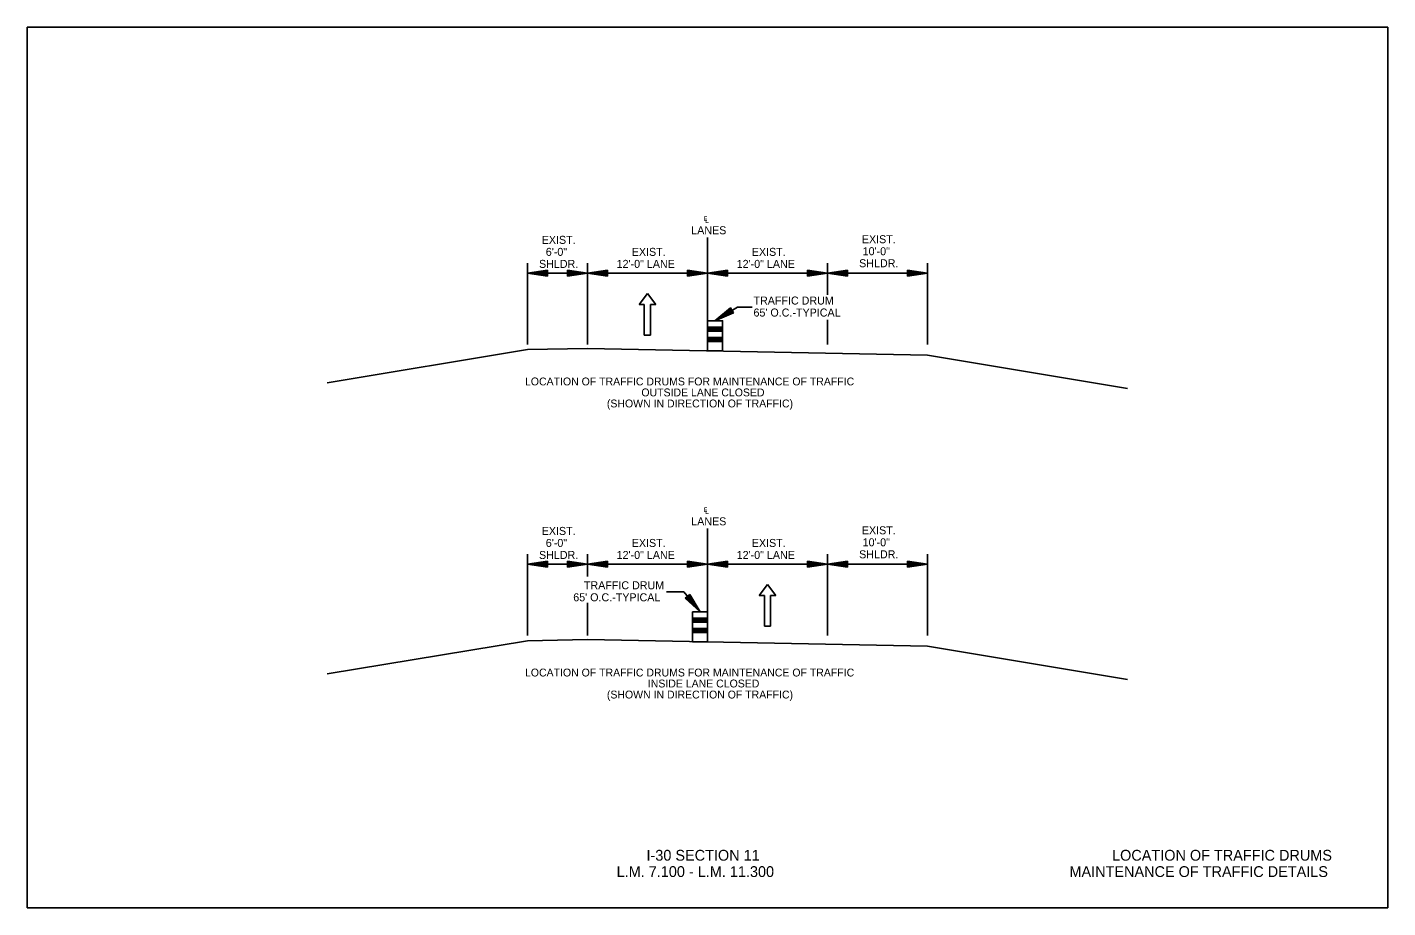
# Model space of a CAD drawing. Extents: x 1374027 to 1374537, y 380415 to 381405.
# Drawn here: x 1374027.1 to 1374197.1, y 380415.2 to 380525.2 of the extents above; entities that cross this region are included whole.
import ezdxf

# ---------------------------------------------------------------- set-up
doc = ezdxf.new("R2010")
doc.units = 0
for name, color, linetype in [('Default', 7, 'Continuous'), ('DSN_DRFT_Common-Annotations', 7, 'Continuous'), ('DSN_DRFT_Common-Line', 7, 'Continuous'), ('DSN_DRFT_Dimension', 7, 'Continuous'), ('DSN_DRFT_Junk-No-Plot', 7, 'Continuous'), ('R_Border Notes', 7, 'Continuous'), ('R_MOT', 7, 'Continuous'), ('R_Striping', 7, 'Continuous')]:
    doc.layers.add(name, color=color, linetype=linetype)

msp = doc.modelspace()

# ---------------------------------------------------------------- linework, layer by layer
at = {"layer": 'DSN_DRFT_Common-Line'}
for p, q in [((1374112.08, 380498.91), (1374112.08, 380488.5)), ((1374089.58, 380495.71), (1374089.58, 380485.55)), ((1374097.08, 380495.71), (1374097.08, 380485.55)), ((1374127.08, 380495.71), (1374127.08, 380491.73)), ((1374139.58, 380495.71), (1374139.58, 380485.55)), ((1374127.08, 380488.62), (1374127.08, 380485.55)), ((1374089.58, 380484.9), (1374064.58, 380480.74)), ((1374097.08, 380485.05), (1374089.58, 380484.9)), ((1374097.08, 380485.05), (1374139.58, 380484.2)), ((1374139.58, 380484.2), (1374164.58, 380480.04)), ((1374112.08, 380462.55), (1374112.08, 380452.14)), ((1374089.58, 380459.35), (1374089.58, 380449.19)), ((1374097.08, 380459.35), (1374097.08, 380456.54)), ((1374127.08, 380459.35), (1374127.08, 380449.19)), ((1374139.58, 380459.35), (1374139.58, 380449.19)), ((1374097.08, 380453.26), (1374097.08, 380449.19)), ((1374089.58, 380448.54), (1374064.58, 380444.38)), ((1374097.08, 380448.69), (1374089.58, 380448.54)), ((1374097.08, 380448.69), (1374139.58, 380447.84)), ((1374139.58, 380447.84), (1374164.58, 380443.68))]:
    msp.add_line(p, q, dxfattribs=at)
at = {"layer": 'DSN_DRFT_Dimension'}
for p, q in [((1374092.08, 380494.84), (1374089.58, 380494.46)), ((1374097.08, 380494.46), (1374089.58, 380494.46)), ((1374092.08, 380494.09), (1374089.58, 380494.46)), ((1374092.08, 380494.78), (1374090, 380494.46)), ((1374092.08, 380494.15), (1374090, 380494.46)), ((1374092.08, 380494.71), (1374090.43, 380494.46)), ((1374092.08, 380494.22), (1374090.43, 380494.46)), ((1374092.08, 380494.65), (1374090.85, 380494.46)), ((1374092.08, 380494.28), (1374090.85, 380494.46)), ((1374092.08, 380494.59), (1374091.27, 380494.46)), ((1374092.08, 380494.34), (1374091.27, 380494.46)), ((1374092.08, 380494.52), (1374091.69, 380494.46)), ((1374092.08, 380494.41), (1374091.69, 380494.46)), ((1374092.08, 380494.84), (1374092.08, 380494.09)), ((1374094.58, 380494.84), (1374097.08, 380494.46)), ((1374094.58, 380494.84), (1374094.58, 380494.09)), ((1374094.58, 380494.78), (1374096.67, 380494.46)), ((1374094.58, 380494.71), (1374096.24, 380494.46)), ((1374094.58, 380494.65), (1374095.82, 380494.46)), ((1374094.58, 380494.59), (1374095.4, 380494.46)), ((1374094.58, 380494.52), (1374094.98, 380494.46)), ((1374094.58, 380494.09), (1374097.08, 380494.46)), ((1374094.58, 380494.34), (1374095.4, 380494.46)), ((1374094.58, 380494.22), (1374096.24, 380494.46)), ((1374094.58, 380494.15), (1374096.67, 380494.46)), ((1374094.58, 380494.28), (1374095.82, 380494.46)), ((1374094.58, 380494.41), (1374094.98, 380494.46)), ((1374099.58, 380494.84), (1374097.08, 380494.46)), ((1374097.08, 380494.46), (1374112.08, 380494.46)), ((1374099.58, 380494.09), (1374097.08, 380494.46)), ((1374099.58, 380494.78), (1374097.5, 380494.46)), ((1374099.58, 380494.15), (1374097.5, 380494.46)), ((1374099.58, 380494.71), (1374097.93, 380494.46)), ((1374099.58, 380494.22), (1374097.93, 380494.46)), ((1374099.58, 380494.65), (1374098.35, 380494.46)), ((1374099.58, 380494.28), (1374098.35, 380494.46)), ((1374099.58, 380494.59), (1374098.77, 380494.46)), ((1374099.58, 380494.34), (1374098.77, 380494.46)), ((1374099.58, 380494.52), (1374099.19, 380494.46)), ((1374099.58, 380494.41), (1374099.19, 380494.46)), ((1374099.58, 380494.84), (1374099.58, 380494.09)), ((1374109.58, 380494.84), (1374112.08, 380494.46)), ((1374109.58, 380494.84), (1374109.58, 380494.09)), ((1374109.58, 380494.78), (1374111.67, 380494.46)), ((1374109.58, 380494.71), (1374111.24, 380494.46)), ((1374109.58, 380494.65), (1374110.82, 380494.46)), ((1374109.58, 380494.59), (1374110.4, 380494.46)), ((1374109.58, 380494.52), (1374109.98, 380494.46)), ((1374109.58, 380494.09), (1374112.08, 380494.46)), ((1374109.58, 380494.34), (1374110.4, 380494.46)), ((1374109.58, 380494.22), (1374111.24, 380494.46)), ((1374109.58, 380494.15), (1374111.67, 380494.46)), ((1374109.58, 380494.28), (1374110.82, 380494.46)), ((1374109.58, 380494.41), (1374109.98, 380494.46)), ((1374114.58, 380494.84), (1374112.08, 380494.46)), ((1374112.08, 380494.46), (1374127.08, 380494.46)), ((1374114.58, 380494.09), (1374112.08, 380494.46)), ((1374114.58, 380494.78), (1374112.5, 380494.46)), ((1374114.58, 380494.15), (1374112.5, 380494.46)), ((1374114.58, 380494.71), (1374112.93, 380494.46)), ((1374114.58, 380494.22), (1374112.93, 380494.46)), ((1374114.58, 380494.65), (1374113.35, 380494.46)), ((1374114.58, 380494.28), (1374113.35, 380494.46)), ((1374114.58, 380494.59), (1374113.77, 380494.46)), ((1374114.58, 380494.34), (1374113.77, 380494.46)), ((1374114.58, 380494.52), (1374114.19, 380494.46)), ((1374114.58, 380494.41), (1374114.19, 380494.46)), ((1374114.58, 380494.84), (1374114.58, 380494.09)), ((1374124.58, 380494.84), (1374127.08, 380494.46)), ((1374124.58, 380494.84), (1374124.58, 380494.09)), ((1374124.58, 380494.78), (1374126.67, 380494.46)), ((1374124.58, 380494.71), (1374126.24, 380494.46)), ((1374124.58, 380494.65), (1374125.82, 380494.46)), ((1374124.58, 380494.59), (1374125.4, 380494.46)), ((1374124.58, 380494.52), (1374124.98, 380494.46)), ((1374124.58, 380494.09), (1374127.08, 380494.46)), ((1374124.58, 380494.34), (1374125.4, 380494.46)), ((1374124.58, 380494.22), (1374126.24, 380494.46)), ((1374124.58, 380494.15), (1374126.67, 380494.46)), ((1374124.58, 380494.28), (1374125.82, 380494.46)), ((1374124.58, 380494.41), (1374124.98, 380494.46)), ((1374129.58, 380494.84), (1374127.08, 380494.46)), ((1374127.08, 380494.46), (1374139.58, 380494.46)), ((1374129.58, 380494.09), (1374127.08, 380494.46)), ((1374129.58, 380494.78), (1374127.5, 380494.46)), ((1374129.58, 380494.15), (1374127.5, 380494.46)), ((1374129.58, 380494.71), (1374127.93, 380494.46)), ((1374129.58, 380494.22), (1374127.93, 380494.46)), ((1374129.58, 380494.65), (1374128.35, 380494.46)), ((1374129.58, 380494.28), (1374128.35, 380494.46)), ((1374129.58, 380494.59), (1374128.77, 380494.46)), ((1374129.58, 380494.34), (1374128.77, 380494.46)), ((1374129.58, 380494.52), (1374129.19, 380494.46)), ((1374129.58, 380494.41), (1374129.19, 380494.46)), ((1374129.58, 380494.84), (1374129.58, 380494.09)), ((1374137.08, 380494.84), (1374139.58, 380494.46)), ((1374137.08, 380494.84), (1374137.08, 380494.09)), ((1374137.08, 380494.78), (1374139.17, 380494.46)), ((1374137.08, 380494.71), (1374138.74, 380494.46)), ((1374137.08, 380494.65), (1374138.32, 380494.46)), ((1374137.08, 380494.59), (1374137.9, 380494.46)), ((1374137.08, 380494.52), (1374137.48, 380494.46)), ((1374137.08, 380494.09), (1374139.58, 380494.46)), ((1374137.08, 380494.34), (1374137.9, 380494.46)), ((1374137.08, 380494.22), (1374138.74, 380494.46)), ((1374137.08, 380494.15), (1374139.17, 380494.46)), ((1374137.08, 380494.28), (1374138.32, 380494.46)), ((1374137.08, 380494.41), (1374137.48, 380494.46)), ((1374113.02, 380488.5), (1374115.85, 380490.22)), ((1374114.96, 380490.12), (1374113.02, 380488.5)), ((1374115.35, 380489.48), (1374113.02, 380488.5)), ((1374114.99, 380490.07), (1374113.38, 380488.72)), ((1374115.32, 380489.54), (1374113.38, 380488.72)), ((1374115.03, 380490.01), (1374113.74, 380488.94)), ((1374115.29, 380489.59), (1374113.74, 380488.94)), ((1374115.06, 380489.96), (1374114.1, 380489.16)), ((1374115.25, 380489.64), (1374114.1, 380489.16)), ((1374115.09, 380489.91), (1374114.46, 380489.38)), ((1374115.22, 380489.7), (1374114.46, 380489.38)), ((1374115.13, 380489.85), (1374114.82, 380489.6)), ((1374115.19, 380489.75), (1374114.82, 380489.6)), ((1374114.96, 380490.12), (1374115.35, 380489.48)), ((1374115.85, 380490.22), (1374117.65, 380490.22)), ((1374092.08, 380458.48), (1374089.58, 380458.1)), ((1374092.08, 380458.42), (1374090, 380458.1)), ((1374092.08, 380458.35), (1374090.43, 380458.1)), ((1374092.08, 380458.48), (1374092.08, 380457.73)), ((1374094.58, 380458.48), (1374097.08, 380458.1)), ((1374094.58, 380458.48), (1374094.58, 380457.73)), ((1374094.58, 380458.42), (1374096.67, 380458.1)), ((1374094.58, 380458.35), (1374096.24, 380458.1)), ((1374099.58, 380458.48), (1374097.08, 380458.1)), ((1374099.58, 380458.42), (1374097.5, 380458.1)), ((1374099.58, 380458.35), (1374097.93, 380458.1)), ((1374099.58, 380458.48), (1374099.58, 380457.73)), ((1374109.58, 380458.48), (1374112.08, 380458.1)), ((1374109.58, 380458.48), (1374109.58, 380457.73)), ((1374109.58, 380458.42), (1374111.67, 380458.1)), ((1374109.58, 380458.35), (1374111.24, 380458.1)), ((1374114.58, 380458.48), (1374112.08, 380458.1)), ((1374114.58, 380458.42), (1374112.5, 380458.1)), ((1374114.58, 380458.35), (1374112.93, 380458.1)), ((1374114.58, 380458.48), (1374114.58, 380457.73)), ((1374124.58, 380458.48), (1374127.08, 380458.1)), ((1374124.58, 380458.48), (1374124.58, 380457.73)), ((1374124.58, 380458.42), (1374126.67, 380458.1)), ((1374124.58, 380458.35), (1374126.24, 380458.1)), ((1374129.58, 380458.48), (1374127.08, 380458.1)), ((1374129.58, 380458.42), (1374127.5, 380458.1)), ((1374129.58, 380458.35), (1374127.93, 380458.1)), ((1374129.58, 380458.48), (1374129.58, 380457.73)), ((1374137.08, 380458.48), (1374139.58, 380458.1)), ((1374137.08, 380458.48), (1374137.08, 380457.73)), ((1374137.08, 380458.42), (1374139.17, 380458.1)), ((1374137.08, 380458.35), (1374138.74, 380458.1)), ((1374097.08, 380458.1), (1374089.58, 380458.1)), ((1374092.08, 380457.73), (1374089.58, 380458.1)), ((1374092.08, 380457.79), (1374090, 380458.1)), ((1374092.08, 380457.86), (1374090.43, 380458.1)), ((1374092.08, 380458.29), (1374090.85, 380458.1)), ((1374092.08, 380457.92), (1374090.85, 380458.1)), ((1374092.08, 380458.23), (1374091.27, 380458.1)), ((1374092.08, 380457.98), (1374091.27, 380458.1)), ((1374092.08, 380458.16), (1374091.69, 380458.1)), ((1374092.08, 380458.05), (1374091.69, 380458.1)), ((1374094.58, 380458.29), (1374095.82, 380458.1)), ((1374094.58, 380458.23), (1374095.4, 380458.1)), ((1374094.58, 380458.16), (1374094.98, 380458.1)), ((1374094.58, 380457.73), (1374097.08, 380458.1)), ((1374094.58, 380457.98), (1374095.4, 380458.1)), ((1374094.58, 380457.86), (1374096.24, 380458.1)), ((1374094.58, 380457.79), (1374096.67, 380458.1)), ((1374094.58, 380457.92), (1374095.82, 380458.1)), ((1374094.58, 380458.05), (1374094.98, 380458.1)), ((1374097.08, 380458.1), (1374112.08, 380458.1)), ((1374099.58, 380457.73), (1374097.08, 380458.1)), ((1374099.58, 380457.79), (1374097.5, 380458.1)), ((1374099.58, 380457.86), (1374097.93, 380458.1)), ((1374099.58, 380458.29), (1374098.35, 380458.1)), ((1374099.58, 380457.92), (1374098.35, 380458.1)), ((1374099.58, 380458.23), (1374098.77, 380458.1)), ((1374099.58, 380457.98), (1374098.77, 380458.1)), ((1374099.58, 380458.16), (1374099.19, 380458.1)), ((1374099.58, 380458.05), (1374099.19, 380458.1)), ((1374109.58, 380458.29), (1374110.82, 380458.1)), ((1374109.58, 380458.23), (1374110.4, 380458.1)), ((1374109.58, 380458.16), (1374109.98, 380458.1)), ((1374109.58, 380457.73), (1374112.08, 380458.1)), ((1374109.58, 380457.98), (1374110.4, 380458.1)), ((1374109.58, 380457.86), (1374111.24, 380458.1)), ((1374109.58, 380457.79), (1374111.67, 380458.1)), ((1374109.58, 380457.92), (1374110.82, 380458.1)), ((1374109.58, 380458.05), (1374109.98, 380458.1)), ((1374112.08, 380458.1), (1374127.08, 380458.1)), ((1374114.58, 380457.73), (1374112.08, 380458.1)), ((1374114.58, 380457.79), (1374112.5, 380458.1)), ((1374114.58, 380457.86), (1374112.93, 380458.1)), ((1374114.58, 380458.29), (1374113.35, 380458.1)), ((1374114.58, 380457.92), (1374113.35, 380458.1)), ((1374114.58, 380458.23), (1374113.77, 380458.1)), ((1374114.58, 380457.98), (1374113.77, 380458.1)), ((1374114.58, 380458.16), (1374114.19, 380458.1)), ((1374114.58, 380458.05), (1374114.19, 380458.1)), ((1374124.58, 380458.29), (1374125.82, 380458.1)), ((1374124.58, 380458.23), (1374125.4, 380458.1)), ((1374124.58, 380458.16), (1374124.98, 380458.1)), ((1374124.58, 380457.73), (1374127.08, 380458.1)), ((1374124.58, 380457.98), (1374125.4, 380458.1)), ((1374124.58, 380457.86), (1374126.24, 380458.1)), ((1374124.58, 380457.79), (1374126.67, 380458.1)), ((1374124.58, 380457.92), (1374125.82, 380458.1)), ((1374124.58, 380458.05), (1374124.98, 380458.1)), ((1374127.08, 380458.1), (1374139.58, 380458.1)), ((1374129.58, 380457.73), (1374127.08, 380458.1)), ((1374129.58, 380457.79), (1374127.5, 380458.1)), ((1374129.58, 380457.86), (1374127.93, 380458.1)), ((1374129.58, 380458.29), (1374128.35, 380458.1)), ((1374129.58, 380457.92), (1374128.35, 380458.1)), ((1374129.58, 380458.23), (1374128.77, 380458.1)), ((1374129.58, 380457.98), (1374128.77, 380458.1)), ((1374129.58, 380458.16), (1374129.19, 380458.1)), ((1374129.58, 380458.05), (1374129.19, 380458.1)), ((1374137.08, 380458.29), (1374138.32, 380458.1)), ((1374137.08, 380458.23), (1374137.9, 380458.1)), ((1374137.08, 380458.16), (1374137.48, 380458.1)), ((1374137.08, 380457.73), (1374139.58, 380458.1)), ((1374137.08, 380457.98), (1374137.9, 380458.1)), ((1374137.08, 380457.86), (1374138.74, 380458.1)), ((1374137.08, 380457.79), (1374139.17, 380458.1)), ((1374137.08, 380457.92), (1374138.32, 380458.1)), ((1374137.08, 380458.05), (1374137.48, 380458.1)), ((1374106.97, 380454.63), (1374109.12, 380454.63)), ((1374109.12, 380454.63), (1374111.15, 380452.14)), ((1374109.86, 380454.32), (1374109.28, 380453.84)), ((1374109.28, 380453.84), (1374111.15, 380452.14)), ((1374109.32, 380453.88), (1374110.88, 380452.47)), ((1374109.37, 380453.92), (1374110.61, 380452.8)), ((1374109.42, 380453.96), (1374110.35, 380453.12)), ((1374109.47, 380454), (1374110.08, 380453.45)), ((1374109.52, 380454.04), (1374109.82, 380453.78)), ((1374109.61, 380454.12), (1374109.82, 380453.78)), ((1374109.66, 380454.16), (1374110.08, 380453.45)), ((1374109.71, 380454.2), (1374110.35, 380453.12)), ((1374109.76, 380454.24), (1374110.61, 380452.8)), ((1374109.81, 380454.28), (1374110.88, 380452.47)), ((1374109.86, 380454.32), (1374111.15, 380452.14))]:
    msp.add_line(p, q, dxfattribs=at)
at = {"layer": 'DSN_DRFT_Junk-No-Plot'}
for points in [[(1374027.08, 380525.17), (1374197.08, 380525.17), (1374197.08, 380415.17), (1374027.08, 380415.17)], [(1374027.08, 380525.17), (1374027.08, 380415.17), (1374197.08, 380415.17), (1374197.08, 380525.17)]]:
    msp.add_lwpolyline(points, close=True, dxfattribs=at)
at = {"layer": 'R_MOT'}
for p, q in [((1374112.08, 380487.7), (1374113.96, 380487.7)), ((1374112.08, 380487.63), (1374113.96, 380487.63)), ((1374112.08, 380487.56), (1374113.96, 380487.56)), ((1374112.08, 380487.5), (1374113.96, 380487.5)), ((1374112.08, 380487.43), (1374113.96, 380487.43)), ((1374112.08, 380487.33), (1374113.96, 380487.33)), ((1374112.08, 380487.25), (1374113.96, 380487.25)), ((1374112.08, 380487.2), (1374113.96, 380487.2)), ((1374112.08, 380486.42), (1374113.96, 380486.42)), ((1374112.08, 380486.35), (1374113.96, 380486.35)), ((1374112.08, 380486.28), (1374113.96, 380486.28)), ((1374112.08, 380486.22), (1374113.96, 380486.22)), ((1374112.08, 380486.14), (1374113.96, 380486.14)), ((1374112.08, 380486.05), (1374113.96, 380486.05)), ((1374112.08, 380485.96), (1374113.96, 380485.96)), ((1374112.08, 380485.91), (1374113.96, 380485.91)), ((1374110.21, 380451.34), (1374112.08, 380451.34)), ((1374110.21, 380451.27), (1374112.08, 380451.27)), ((1374110.21, 380451.2), (1374112.08, 380451.2)), ((1374110.21, 380451.14), (1374112.08, 380451.14)), ((1374110.21, 380451.07), (1374112.08, 380451.07)), ((1374110.21, 380450.97), (1374112.08, 380450.97)), ((1374110.21, 380450.89), (1374112.08, 380450.89)), ((1374110.21, 380450.84), (1374112.08, 380450.84)), ((1374110.21, 380450.06), (1374112.08, 380450.06)), ((1374110.21, 380449.99), (1374112.08, 380449.99)), ((1374110.21, 380449.92), (1374112.08, 380449.92)), ((1374110.21, 380449.86), (1374112.08, 380449.86)), ((1374110.21, 380449.78), (1374112.08, 380449.78)), ((1374110.21, 380449.69), (1374112.08, 380449.69)), ((1374110.21, 380449.6), (1374112.08, 380449.6)), ((1374110.21, 380449.55), (1374112.08, 380449.55))]:
    msp.add_line(p, q, dxfattribs=at)
for points in [[(1374112.08, 380488.5), (1374113.96, 380488.5), (1374113.96, 380484.75), (1374112.08, 380484.75)], [(1374110.21, 380452.14), (1374112.08, 380452.14), (1374112.08, 380448.39), (1374110.21, 380448.39)]]:
    msp.add_lwpolyline(points, close=True, dxfattribs=at)
at = {"layer": 'R_Striping'}
for p, q in [((1374103.54, 380490.55), (1374104.58, 380491.9)), ((1374104.58, 380491.9), (1374105.62, 380490.55)), ((1374103.54, 380490.55), (1374104.19, 380490.55)), ((1374104.19, 380490.55), (1374104.19, 380486.72)), ((1374104.97, 380490.55), (1374104.97, 380486.72)), ((1374104.97, 380490.55), (1374105.62, 380490.55)), ((1374104.19, 380486.72), (1374104.97, 380486.72)), ((1374118.54, 380454.19), (1374119.58, 380455.54)), ((1374119.58, 380455.54), (1374120.62, 380454.19)), ((1374118.54, 380454.19), (1374119.19, 380454.19)), ((1374119.19, 380454.19), (1374119.19, 380450.36)), ((1374119.97, 380454.19), (1374119.97, 380450.36)), ((1374119.97, 380454.19), (1374120.62, 380454.19)), ((1374119.19, 380450.36), (1374119.97, 380450.36))]:
    msp.add_line(p, q, dxfattribs=at)

# ---------------------------------------------------------------- texts
at = {"layer": 'Default'}
for s, p in [('LOCATION OF TRAFFIC DRUMS FOR MAINTENANCE OF TRAFFIC', (1374089.28, 380480.43)), ('(SHOWN IN DIRECTION OF TRAFFIC)', (1374099.51, 380477.68)), ('OUTSIDE LANE CLOSED', (1374103.82, 380479.06)), ('LOCATION OF TRAFFIC DRUMS FOR MAINTENANCE OF TRAFFIC', (1374089.28, 380444.07)), ('INSIDE LANE CLOSED', (1374104.63, 380442.7)), ('(SHOWN IN DIRECTION OF TRAFFIC)', (1374099.51, 380441.32))]:
    msp.add_text(s, height=0.9817, dxfattribs=at).set_placement(p)
at = {"layer": 'DSN_DRFT_Common-Annotations'}
for s, p in [('℄', (1374111.57, 380500.81)), ('EXIST.', (1374091.37, 380498.11)), ('LANES', (1374110.05, 380499.31)), ('EXIST.', (1374131.37, 380498.19)), ('6\'-0"', (1374091.88, 380496.61)), ('EXIST.', (1374102.62, 380496.61)), ('EXIST.', (1374117.62, 380496.61)), ('10\'-0"', (1374131.47, 380496.69)), ('SHLDR.', (1374091.03, 380495.11)), ('12\'-0" LANE', (1374100.73, 380495.11)), ('12\'-0" LANE', (1374115.73, 380495.11)), ('SHLDR.', (1374131.03, 380495.19)), ('TRAFFIC DRUM', (1374117.83, 380490.53)), ("65' O.C.-TYPICAL", (1374117.83, 380489.03)), ('℄', (1374111.57, 380464.45)), ('LANES', (1374110.05, 380462.95)), ('EXIST.', (1374091.37, 380461.75)), ('EXIST.', (1374131.37, 380461.83)), ('6\'-0"', (1374091.88, 380460.25)), ('EXIST.', (1374102.62, 380460.25)), ('EXIST.', (1374117.62, 380460.25)), ('10\'-0"', (1374131.47, 380460.33)), ('SHLDR.', (1374091.03, 380458.75)), ('12\'-0" LANE', (1374100.73, 380458.75)), ('12\'-0" LANE', (1374115.73, 380458.75)), ('SHLDR.', (1374131.03, 380458.83)), ('TRAFFIC DRUM', (1374096.64, 380454.96)), ("65' O.C.-TYPICAL", (1374095.31, 380453.46))]:
    msp.add_text(s, height=1, dxfattribs=at).set_placement(p)
at = {"layer": 'R_Border Notes'}
for s, p in [('I-30 SECTION 11', (1374104.46, 380421.06)), ('LOCATION OF TRAFFIC DRUMS', (1374162.63, 380421.06)), ('L.M. 7.100 - L.M. 11.300', (1374100.73, 380419.02)), ('MAINTENANCE OF TRAFFIC DETAILS', (1374157.31, 380419.02))]:
    msp.add_text(s, height=1.35, dxfattribs=at).set_placement(p)

doc.saveas('drawing.dxf')
